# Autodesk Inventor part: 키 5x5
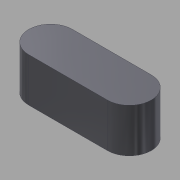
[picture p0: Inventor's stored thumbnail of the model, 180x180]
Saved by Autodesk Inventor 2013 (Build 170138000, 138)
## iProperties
Created: 2014-10
Part Number: 키 5x5
Document SubType Name: Modeling
Designer: KYOUNG IL JANG
Density: 1 g/cm^3
Mass: 0.323175 g
Surface Area: 2.9781 cm^2
Volume: 0.323175 cm^3
Material: 강철, 연강
Author: SeoGD™ [www.esajin.kr]
Revision Number: 1
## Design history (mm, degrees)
sketch "스케치1"
  geometry: L1 (-4.5, -2.5)-(4.5, -2.5); L2 (4.5, 2.5)-(-4.5, 2.5); A1 r 2.5 centre (4.5, 0) between (4.5, -2.5) and (4.5, 2.5); A2 r 2.5 centre (-4.5, 0) between (-4.5, 2.5) and (-4.5, -2.5); 2 further points
  constraints: 4 end point, 4 point on circle, 4 tangent, 2 centre point, 1 horizontal, 1 horizontal alignment, 1 midpoint, 1 parallel, 1 vertical alignment
  dimensions: "d0" = 5 distance between parallel lines of L1 L2; "d1" = 14 dimension on A1 A2
extrude "돌출1" new body sketch "스케치1" stored distance "d2" = 5; taper "d3" = 0 deg
node "솔리드1"
